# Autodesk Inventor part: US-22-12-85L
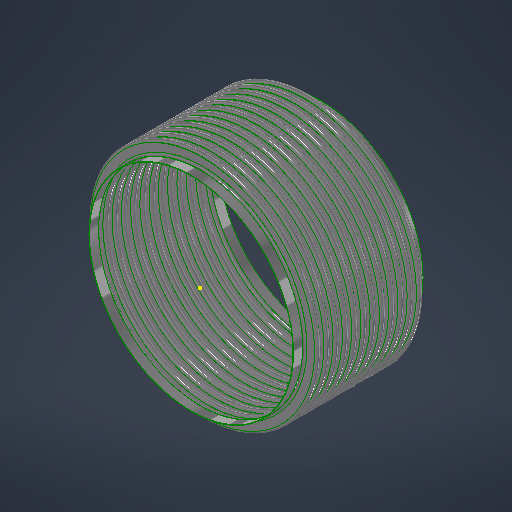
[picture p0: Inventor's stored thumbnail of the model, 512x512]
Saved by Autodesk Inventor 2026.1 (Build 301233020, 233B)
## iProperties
Category: 18 GA (0.048 THICK)
RuleStatus: InUse
Created: 2026-07
Part Number: US-22-12-85L
Project: =STOCK BELLOWS: <Stock Number><SFILL>
Material: ASTM A240-304
Description: =STOCK BELLOWS: <Stock Number>, <SID_> I.D., <SOD_> O.D., <SPLY_> PLY, <Category>, <SNET_CONS> CONS.<PITCH_><STANGENT_> TANGENT<SFILL>
Document SubType Name: Sheet Metal
Designer: LC
Stock Number: U.S-22-12-85L
Surface Area: 659.127 cm^2
Volume: 56.61 cm^3
Sheet Metal Rule: Default
Appearance: STAINLESS STEEL
NET_TUBE: 3.428
COUNTER: 1.500
PBAR: 1.214
PSET: 5.356
PLY: 2
CONS: 2
THK: 0.036
ID: 4.500
OD: 5.500
CONS_: 2
TANGENT: 0.500
PITCH: 0.375
BELLOWS_UPSET: 0.000
NET_CONS: 2
S_CONS: 0
Description_Units: 0
ID_M: 114.30 mm
OD_M: 139.70 mm
THK_M: 0.91 mm
ID_U: 4.500 in
OD_U: 5.500 in
THK_U: 0.036 in
TANGENT2: 0.500
d79: 1.000
d82: 1.000
d83: 26.000
d84: 24.000
d80: 2.571
d81: 10
SID: 2.375
SCONS_: 12
SPITCH: 0.250
SBELLOWS_UPSET: 0.000
SNET_CONS: 12
SS_CONS: 0
SCONS: 8
d174: 8
d177: 0.018
d178: 2.375
d179: 3.000
d180: 0.375
d181: 1.000
d182: 0.000
d190: 8
d191: 1
d192: 1
d193: 8
d194: 0
PART_NUMBER: U.S-22-12-85L
PRESSURE: 85
SIZE: 22.00
STANGENT_: 1.000
d214: 8
d217: 0.030
d218: 6.625
d219: 8.125
d220: 0.500
d221: 1.000
d222: 0.000
d230: 8
d231: 1
d232: 1
d233: 8
d234: 0
STANGENT: 4.000
SPLY_: 1
STHK_: 0.048
SID_: 22.000
SOD_: 24.750
SPITCH_: 1.000
STANGENT__: 1.000
SBELLOWS_UPSET_: 0.000
SDIFF_TAN: 1.000
TAN_TO_TAN: 0.750 in
d252: 2
d275: 2
d287: 0.050
d289: 0.500
d290: 0.000
d263: 2
d265: 1
d268: 2
d269: 0
d286: 2
d288: 1
d291: 2
d292: 0
SOD_NECK: 22 1/8
CFILL: .
SFILL: .
PITCH_: =, <SPITCH_> PITCH,
SREROLL: 0.750
MATTABLE: 20 GA (0.036 THICK)
MESH: ,
CSECT: 2
Author: LC
Keywords: 20 GA (0.036 THICK)
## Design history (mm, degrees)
sketch "Sketch2"
  geometry: L1 (0, -183.595)-(0, 600.956) reference; L2 (58.979, 0)-(57.15, 0); L3 (60.446, -1.467)-(66.554, -1.467); L4 (60.446, -3.296)-(66.554, -3.296); L5 (66.554, -8.058)-(60.446, -8.058); L6 (66.554, -6.229)-(60.446, -6.229); L7 (58.979, -9.525)-(57.15, -9.525); L8 (60.446, 0)-(60.446, -9.525); L9 (66.554, -4.762)-(69.85, -4.763); L10 (57.15, 0)-(57.15, -9.525); L11 (20.376, 102.841)-(20.376, 101.926); L12 (58.262, 488.877)-(58.262, 349.177); L13 (58.262, 479.352)-(58.262, 339.652); L14 (93.133, -58.817)-(93.133, -71.517); L15 (118.746, -66.401)-(118.746, -66.401); L16 (66.554, -6.229)-(66.554, -8.058); L17 (60.446, -6.229)-(60.446, -8.058); L18 (60.446, -7.144)-(66.554, -7.144); L19 (69.85, 0)-(69.85, -9.525); L20 (-66.554, -6.229)-(-66.554, -8.058); L21 (-66.554, -1.467)-(-60.446, -1.467); L22 (-66.554, -3.296)-(-60.446, -3.296); L23 (-60.446, -6.229)-(-66.554, -6.229); L24 (-66.554, -7.144)-(-60.446, -7.144); L25 (-60.446, -8.058)-(-66.554, -8.058); L26 (-60.446, -6.229)-(-60.446, -8.058); L27 (-57.15, -2.522)-(-57.15, -12.047); L28 (-60.446, -4.763)-(-57.15, -4.763); L29 (-66.554, 3.828)-(-66.554, -9.525); L30 (-68.021, 0)-(-69.85, 0); L31 (-69.85, 0)-(-69.85, -9.525); L32 (-68.021, -9.525)-(-69.85, -9.525); A1 r 1.467 centre (60.446, 0) between (58.979, 0) and (60.446, -1.467); A2 r 3.296 centre (60.446, 0) between (57.15, 0) and (60.446, -3.296); A3 r 3.296 centre (66.554, -4.762) between (66.554, -8.058) and (66.554, -1.467); A4 r 1.467 centre (66.554, -4.762) between (66.554, -6.229) and (66.554, -3.296); A5 r 1.467 centre (60.446, -9.525) between (60.446, -8.058) and (58.979, -9.525); A6 r 3.296 centre (60.446, -9.525) between (60.446, -6.229) and (57.15, -9.525); A7 r 2.381 centre (66.554, -4.762) between (66.554, -7.144) and (68.936, -4.762); A8 r 2.381 centre (60.446, -9.525) between (60.446, -7.144) and (58.064, -9.525); A9 r 1.467 centre (-66.554, -9.525) between (-66.554, -8.058) and (-68.021, -9.525); A10 r 1.467 centre (-60.446, -4.763) between (-60.446, -6.229) and (-60.446, -3.296); A11 r 2.381 centre (-60.446, -4.763) between (-60.446, -7.144) and (-58.064, -4.763); A12 r 3.296 centre (-60.446, -4.763) between (-60.446, -8.058) and (-60.446, -1.467); A13 r 2.381 centre (-66.554, -9.525) between (-66.554, -7.144) and (-68.936, -9.525); A14 r 3.296 centre (-66.554, -9.525) between (-66.554, -6.229) and (-69.85, -9.525); A15 r 1.467 centre (-66.554, 0) between (-68.021, 0) and (-66.554, -1.467); A16 r 3.296 centre (-66.554, 0) between (-69.85, 0) and (-66.554, -3.296); 10 further points
  constraints: 62 end point, 38 point on circle, 20 tangent, 16 centre point, 12 parallel, 9 midpoint, 7 vertical, 6 coincident, 6 concentric, 6 point on line, 4 equal radius, 4 perpendicular, 3 horizontal, 1 collinear, 1 horizontal alignment, 10 other
  dimensions: "THK" = 0.9144 distance of L11.start L11.end; "ID" = 114.3 distance of L11.end point (20.376, -12.374); "OD" = 139.7 distance of L12.start L12.end; "PITCH" = 9.525 distance of L12.start L13.start; "TANGENT" = 12.7 distance of L14.start L14.end; "BELLOWS_UPSET" = 0 distance of L15.start L15.end; "d43" = 114.3 diameter of L10 L1 (= ID); "d44" = 139.7 diameter of L9.end L1 (= OD); "d45" = 1.8288 distance between parallel lines of L5 L6 (computed from THK, PLY); "d46" = 3.29565 radius of A3 (computed from PITCH, THK, PLY); "UPSET_PITCH" = 9.525 distance of L2.end L7.end (derived); "SIDEWALL_ANGLE" = 0 deg angle of L3 L9 (derived); "CON_GAP" = 2.9337 distance of point (60.446, -6.229) point (60.446, -3.296) (derived); "TAN1" = 3.74046 dimension on A8 (derived); "TAN2" = 3.74046 dimension on A7 (derived); "LEG1" = 6.1087 distance of L18.start L18.end (derived); "d278" = 1.8288 distance between parallel lines of L25 L23 (derived); "d279" = 3.29565 radius of A12 (derived); "d280" = 9.525 distance of L30.end L31.end (derived); "d281" = 360 deg dimension on L21 L28 (derived); "d282" = 2.9337 distance of point (-66.554, -6.229) point (-66.554, -3.296) (derived); "d283" = 3.74046 dimension on A13 (derived); "d284" = 3.74046 dimension on A11 (derived); "d285" = 6.1087 distance of L24.start L24.end (derived); "d293" = 114.3 diameter of L27 L1 (derived); "d294" = 139.7 diameter of L31 L1 (derived)
  node "Sketch Rectangular Pattern1" dims "d31" = 25.4, "ID" = 114.3
  node "Sketch Rectangular Pattern2" dims "d39" = 25.4, "PITCH" = 9.525
revolve "CONS" stored, may be unused: angle "d48" = 90 deg
node "BELLOW MIDPLANE"
pattern_linear "Rectangular Pattern2" dims "d52" = 9.525 (= UPSET_PITCH)
sketch "Sketch5"
  geometry: C1 r 58.979 at (0, 0) reference; C2 r 57.15 at (0, 0) reference
extrude "TANGENT" new body sketch "Sketch5" distance "d53" = 12.7 (= TANGENT); taper "d54" = 0 deg
revolve "SAMETAN" stored, may be unused: angle "d65" = 90 deg
revolve "DIFFTAN" stored, may be unused: angle "d70" = 90 deg
sketch "Sketch9"
  geometry: L1 (58.391, 0)-(-58.391, 0) reference; L2 (0, -17.78)-(0, 17.78) reference; L3 (41.708, 0)-(-41.708, 0); L4 (41.708, -11.906)-(41.708, 11.906); L5 (29.008, -11.906)-(29.008, 11.906); L6 (15.418, 11.906)-(15.418, -11.906); L7 (-29.008, -11.906)-(-29.008, 11.906); L8 (-41.708, -11.906)-(-41.708, 11.906); L9 (40.914, -11.906)-(40.914, 11.906); L10 (41.708, -11.906)-(40.914, -11.906); L11 (41.708, 11.906)-(40.914, 11.906); L12 (15.815, 11.906)-(15.022, 11.906); L13 (15.022, 11.906)-(15.022, -11.906); L14 (15.022, -11.906)-(15.815, -11.906); L15 (15.815, -11.906)-(15.815, 11.906); L16 (-15.815, 11.906)-(-15.815, -11.906); L17 (-15.418, 11.906)-(-15.418, -11.906); L18 (-15.815, -11.906)-(-15.022, -11.906); L19 (-15.022, -11.906)-(-15.022, 11.906); L20 (-15.022, 11.906)-(-15.815, 11.906); L21 (-41.708, -11.906)-(-40.914, -11.906); L22 (-40.914, -11.906)-(-40.914, 11.906); L23 (-40.914, 11.906)-(-41.708, 11.906); L24 (-41.708, 11.906)-(-41.708, -11.906); L25 (41.708, -0.397)-(-41.708, -0.397); L26 (-41.708, -0.397)-(-41.708, 0.397); L27 (-41.708, 0.397)-(41.708, 0.397); L28 (41.708, 0.397)-(41.708, -0.397); L29 (-41.708, 11.906)-(41.708, 11.906); L30 (41.708, 11.906)-(41.708, 12.7); L31 (41.708, 12.7)-(-41.708, 12.7); L32 (-41.708, 12.7)-(-41.708, 11.906); L33 (41.708, -11.906)-(-41.708, -11.906); L34 (-41.708, -11.906)-(-41.708, -12.7); L35 (-41.708, -12.7)-(41.708, -12.7); L36 (41.708, -12.7)-(41.708, -11.906); 30 further points
  constraints: 68 end point, 13 midpoint, 13 parallel, 8 horizontal, 7 perpendicular, 6 equal length, 3 point on line, 2 vertical, 14 other
  dimensions: "d115" = 23.8125 distance of L4.start L4.end (derived); "d116" = 12.7 distance between parallel lines of L4 L5 (derived); "d117" = 13.58962 distance between parallel lines of L5 L6 (derived); "d125" = 44.42645 distance between parallel lines of L7 L6 (derived); "d127" = 12.7 distance between parallel lines of L8 L7 (derived); "d128" = 26.28962 distance between parallel lines of L6 L4 (derived); "d130" = 83.41607 distance between parallel lines of L8 L4 (derived); "RULER_THK" = 0.79375 distance between parallel lines of L4 L9; "d135" = 0.79375 distance of L13.end L14.end (derived); "d138" = 30.83684 distance of L13.end L16.end (derived); "d143" = 0.79375 distance of L22.end L8.end (derived); "d144" = 0.79375 distance between parallel lines of L27 L25 (derived)
extrude "RULER" join sketch "Sketch9" distance "d149" = 0.79375 (derived); taper "d150" = 0 deg
extrude "BARS" join sketch "Sketch9" distance "d151" = 0.79375 (derived); taper "d152" = 0 deg
pattern_linear "Rectangular Pattern4" dims "d155" = 30.83684 (derived)
sketch "Sketch13"
  geometry: L1 (93.149, -52.467)-(93.149, -77.867); L2 (280.619, 0)-(279.4, 0); L3 (280.619, -25.4)-(279.4, -25.4); L4 (307.365, -19.66)-(286.36, -19.66); L5 (307.365, -18.44)-(286.36, -18.44); L6 (307.365, -12.7)-(314.325, -12.7); L7 (286.36, -5.74)-(307.365, -5.74); L8 (286.36, 0)-(286.36, -25.4); L9 (279.4, 0)-(279.4, -25.4); L10 (58.254, -184.223)-(58.254, -812.873); L11 (58.254, -209.623)-(58.254, -838.273); L12 (58.254, -260.423)-(58.254, -889.073); L13 (58.254, -285.823)-(58.254, -914.473); L14 (58.254, -311.223)-(58.254, -939.873); L15 (58.254, -336.623)-(58.254, -965.273); L16 (58.254, -362.023)-(58.254, -990.673); L17 (58.254, -235.023)-(58.254, -863.673); L18 (20.376, 103.145)-(20.376, 101.926); L19 (286.36, -6.96)-(307.365, -6.96); L20 (0, -1163.716)-(0, 314.289) reference; L21 (-57.15, 0)-(342.9, 0) reference; A1 r 5.74 centre (286.36, 0) between (280.619, 0) and (286.36, -5.74); A2 r 5.74 centre (286.36, -25.4) between (286.36, -19.66) and (280.619, -25.4); A3 r 6.96 centre (286.36, -25.4) between (286.36, -18.44) and (279.4, -25.4); A4 r 5.74 centre (307.365, -12.7) between (307.365, -18.44) and (307.365, -6.96); A5 r 6.96 centre (307.365, -12.7) between (307.365, -19.66) and (307.365, -5.74); A6 r 6.96 centre (286.36, 0) between (279.4, 0) and (286.36, -6.96); 6 further points; 1 other entity
  constraints: 38 end point, 15 point on circle, 9 tangent, 6 centre point, 6 parallel, 5 vertical alignment, 4 point on line, 4 vertical, 3 coincident, 3 concentric, 2 collinear, 2 equal radius, 1 horizontal, 1 perpendicular, 23 other
  dimensions: "SBELLOWS_UPSET_" = 0 distance of point (118.762, -66.401) point (118.762, -66.401); "STOTAL_THK_BELLOW__" = 1.2192 distance between parallel lines of L4 L5 (derived); "d224" = 6.9596 radius of A5 (derived); "d225" = 25.4 distance of L2.end L3.end (derived); "SSIDEWALL_ANGLE_" = 0 deg angle of L7 L6 (derived); "SSCON_GAP_" = 11.4808 distance of point (286.36, -18.44) point (286.36, -6.96) (derived); "d235" = 558.8 diameter of L9 L20 (derived); "d236" = 628.65 diameter of L6.end L20 (derived)
  node "Sketch Rectangular Pattern4" dims "d228" = 25.4
  node "Sketch Rectangular Pattern5" dims "d229" = 25.4
revolve "SBELLOW" stored, may be unused: angle "d197" = 90 deg
pattern_linear "Rectangular Pattern5" dims "d204" = 25.4 (derived)
revolve "STANGENT" stored, may be unused: angle "d240" = 90 deg
revolve "SSAMETAN" stored, may be unused: angle "d241" = 90 deg
revolve "SDIFFTAN" stored, may be unused: angle "d246" = 90 deg
revolve "INVCON" stored, may be unused: angle "d295" = 90 deg
pattern_linear "Rectangular Pattern6" dims "d298" = 9.525 (derived)
revolve "INVTANGENT" stored, may be unused: angle "d302" = 90 deg
revolve "INVSAMETAN" stored, may be unused: angle "d307" = 90 deg
revolve "INVDIFFTAN" stored, may be unused: angle "d312" = 90 deg
sketch "ID BELLOW MOUNT CALC"
  geometry: L1 (44.45, 0)-(38.1, 0); L2 (38.1, 0)-(38.1, 12.7); L3 (38.1, 12.7)-(44.45, 12.7); L4 (44.45, 12.7)-(44.45, 0); L5 (36.513, 12.7)-(34.684, 12.7); L6 (34.684, 12.7)-(34.684, 0); L7 (34.684, 0)-(36.513, 0); L8 (36.513, 0)-(36.513, 12.7); L9 (0, -2.54)-(0, 15.24) reference; L10 (-8.89, 0)-(53.34, 0) reference; 1 further point
  constraints: 16 end point, 5 parallel, 2 collinear, 2 horizontal, 2 perpendicular
  dimensions: "d314" = 12.7 distance of L5.end L6.end (derived); "d315" = 1.8288 distance of L5.start L5.end (derived); "IG" = 1.5875 distance between parallel lines of L2 L8; "PIPE_OD" = 88.9 diameter of L4 L9; "PIPE_WALL" = 6.35 distance of L2.end L3.end; "ID_MT_BELLOW" = 69.3674 diameter of L6 L9 (derived)
revolve "CFILL" stored, may be unused: angle "d320" = 90 deg
pattern_linear "Rectangular Pattern7" dims "d323" = 9.525 (derived)
revolve "SFILL" stored, may be unused: angle "d324" = 90 deg
pattern_linear "Rectangular Pattern8" dims "d327" = 25.4 (derived)
node "STOCK BELLOW MIDPLANE"
sketch "Sketch21"
  geometry: L1 (0, -100.013)-(0, 100.013) reference; L2 (-100.013, 0)-(100.013, 0) reference; L3 (-0.099, 71.437)-(0.099, 71.437); L4 (0.099, 71.437)-(0.099, 55.562); L5 (0.099, 55.562)-(-0.099, 55.562); L6 (-0.099, 55.562)-(-0.099, 71.437); C1 r 55.562 at (0, 0); C2 r 71.437 at (0, 0); 3 further points
  constraints: 8 end point, 2 centre point, 2 coincident, 2 parallel, 2 tangent, 1 horizontal, 1 perpendicular, 1 other
  dimensions: "d329" = 111.125 diameter of C1 (derived); "d330" = 142.875 diameter of C2 (derived); "d331" = 0.19844 distance of L3.start L3.end
extrude "CLAMSHELL" cut sketch "Sketch21" extent not by distance; stored distance "d332" = 0; taper "d333" = 0 deg
pattern_circular "Circular Pattern1" dims angle "d335" = 180 deg (derived)
node "BELLOW"
sketch "Sketch6"
  geometry: L1 (-19.05, 58.979)-(-6.35, 58.979); L2 (-6.35, 58.979)-(-6.35, 57.15); L3 (-6.35, 57.15)-(-19.05, 57.15); L4 (-19.05, 57.15)-(-19.05, 58.979); L5 (2.54, 0)-(-59.69, 0) reference; L6 (-38.1, -108.388)-(-38.1, 156.601) reference; 1 further point
  constraints: 8 end point, 2 parallel, 1 horizontal, 1 perpendicular
  dimensions: "d61" = 12.7 distance of L2.end L3.end (derived); "d62" = 1.8288 distance of L1.end L2.end (derived); "d63" = 114.3 diameter of L3 L5 (derived); "d64" = 19.05 distance between parallel lines of L4 L6 (derived)
sketch "Sketch12"
  geometry: 1 further point
sketch "Sketch14"
  geometry: L1 (-25.4, 280.619)-(0, 280.619); L2 (0, 280.619)-(0, 279.4); L3 (0, 279.4)-(-25.4, 279.4); L4 (-25.4, 279.4)-(-25.4, 280.619); L5 (5.08, 0)-(-30.48, 0) reference; L6 (0, -51.044)-(0, 306.263) reference; 1 further point
  constraints: 8 end point, 2 parallel, 1 collinear, 1 horizontal, 1 perpendicular
  dimensions: "d237" = 1.2192 distance of L3.end L1.start (derived); "d238" = 558.8 diameter of L3 L5 (derived); "d239" = 25.4 distance of L1.start L1.end (derived); "SOD_NECK" = 561.2384 diameter of L1 L5 (derived)
sketch "Sketch15"
  geometry: L1 (-51.044, 0)-(306.263, 0) reference; L2 (279.4, -304.8)-(280.619, -304.8); L3 (280.619, -304.8)-(280.619, -330.2); L4 (280.619, -330.2)-(279.4, -330.2); L5 (279.4, -330.2)-(279.4, -304.8); L6 (0, -398.78)-(0, 81.28) reference; 1 further point
  constraints: 8 end point, 2 parallel, 1 horizontal, 1 perpendicular
  dimensions: "d205" = 25.4 distance of L4.end L2.start (derived); "d206" = 1.2192 distance of L3.end L4.end (derived); "d207" = 558.8 diameter of L5 L6 (derived); "d208" = 304.8 distance between parallel lines of L1 L2 (derived)
node "TANGENT_"
node "SAME_TAN"
sketch "Sketch8"
  geometry: L1 (58.979, -19.05)-(57.15, -19.05); L2 (57.15, -19.05)-(57.15, -31.75); L3 (57.15, -31.75)-(58.979, -31.75); L4 (58.979, -31.75)-(58.979, -19.05); L5 (0, -40.64)-(0, 21.59) reference; L6 (-108.388, 0)-(156.601, 0) reference; 1 further point
  constraints: 8 end point, 2 parallel, 1 horizontal, 1 perpendicular
  dimensions: "d66" = 114.3 diameter of L2 L5 (derived); "TOTAL_THK_BELLOW" = 1.8288 distance of L2.end L3.end (derived); "d68" = 19.05 distance between parallel lines of L1 L6 (derived); "d69" = 12.7 distance of L1.end L2.end (derived)
node "DIFF_TAN"
node "Sketch Rectangular Pattern3" dims "d138" = 30.83684 (derived), "d141" = 25.4
node "SBELLOW_"
node "STANGENT_"
node "SSAME_TAN"
sketch "Sketch16"
  geometry: L1 (280.619, -304.8)-(279.4, -304.8); L2 (279.4, -304.8)-(279.4, -330.2); L3 (279.4, -330.2)-(280.619, -330.2); L4 (280.619, -330.2)-(280.619, -304.8); L5 (0, -398.78)-(0, 81.28) reference; L6 (-51.044, 0)-(306.263, 0) reference; 1 further point
  constraints: 8 end point, 2 parallel, 1 horizontal, 1 perpendicular
  dimensions: "SDIFF_TAN" = 25.4 distance of L3.end L1.start; "d243" = 1.2192 distance of L2.end L3.end (derived); "d244" = 304.8 distance between parallel lines of L1 L6 (derived); "d245" = 558.8 diameter of L2 L5 (derived)
node "SDIFF_TAN"
body "Solid15"
sketch "Sketch17"
  geometry: L1 (69.85, 12.7)-(68.021, 12.7); L2 (68.021, 12.7)-(68.021, 0); L3 (68.021, 0)-(69.85, 0); L4 (69.85, 0)-(69.85, 12.7); L5 (0, -2.54)-(0, 15.24) reference; L6 (-13.97, 0)-(83.82, 0) reference; 2 further points
  constraints: 8 end point, 2 parallel, 1 horizontal, 1 midpoint, 1 perpendicular, 1 point on line
  dimensions: "INVTANGENT" = 12.7 distance of L3.end L1.start (derived); "d300" = 1.8288 distance of L1.start L1.end (derived); "d301" = 139.7 diameter of L4 L5 (derived)
body "Solid16"
sketch "Sketch18"
  geometry: L1 (69.85, -19.05)-(68.021, -19.05); L2 (68.021, -19.05)-(68.021, -31.75); L3 (68.021, -31.75)-(69.85, -31.75); L4 (69.85, -31.75)-(69.85, -19.05); L5 (-13.97, 0)-(83.82, 0) reference; L6 (0, -40.64)-(0, 21.59) reference; 1 further point
  constraints: 8 end point, 2 parallel, 1 horizontal, 1 perpendicular
  dimensions: "d303" = 19.05 distance between parallel lines of L1 L5 (derived); "d304" = 12.7 distance of L3.end L1.start (derived); "d305" = 1.8288 distance of L2.end L3.end (derived); "d306" = 139.7 diameter of L4 L6 (derived)
body "Solid17"
sketch "Sketch19"
  geometry: L1 (69.85, -19.05)-(68.021, -19.05); L2 (68.021, -19.05)-(68.021, -31.75); L3 (68.021, -31.75)-(69.85, -31.75); L4 (69.85, -31.75)-(69.85, -19.05); L5 (0, -40.64)-(0, 21.59) reference; L6 (-13.97, 0)-(83.82, 0) reference; 1 further point
  constraints: 8 end point, 2 parallel, 1 horizontal, 1 perpendicular
  dimensions: "d308" = 12.7 distance of L1.end L2.end (derived); "d309" = 139.7 diameter of L4 L5 (derived); "d310" = 1.8288 distance of L2.end L3.end (derived); "d311" = 19.05 distance between parallel lines of L1 L6 (derived)
body "Solid18"
body "Solid19"
body "Solid20"
other parameters: "BMPL" = -152.4, "PSET" = 136.0424 (computed from OD, THK, PLY) [user parameter], "PBAR" = 30.83684 (= 0.570796 x PITCH + OD - ID) [user parameter; used in 1 equation term], "COUNTER" = 15 [user parameter], "NET_TUBE" = 87.07367 (computed from CONS_, PBAR, TANGENT) [user parameter], "S_CONS" = 0 [user parameter; used in 1 equation term], "ID_M" = 114.3 (= ID) [user parameter], "OD_M" = 139.7 (= OD) [user parameter], "THK_M" = 0.9144 (= THK) [user parameter], "ID_U" = 114.3 (= ID) [user parameter], "OD_U" = 139.7 (= OD) [user parameter], "THK_U" = 0.9144 (= THK) [user parameter], "D_UNITS" = 0 [user parameter], "TANGENT2" = 12.7 [user parameter], "TAN_TO_TAN" = 19.05 [user parameter], "OD_NECK" = 117.9576 [user parameter], "d79" = 25.4, "d80" = 65.29823 [user parameter], "d82" = 25.4, "d83" = 660.4, "d84" = 609.6, "sa_0" = 4, "FRAME_THK" = 0.79375 [user parameter], "CON_FLAT" = 13.58962 [user parameter], "SID" = 60.325 [user parameter], "SPITCH" = 6.35 [user parameter], "STANGENT_" = 25.4 [user parameter], "SBELLOWS_UPSET" = 0 [user parameter], "SS_CONS" = 0 [user parameter], "STAN_TO_TAN_" = 304.8 [user parameter], "d100" = 1.2192 [user parameter], "d191" = 25.4 [user parameter], "d194" = 0 [user parameter], "STANGENT" = 101.6 [user parameter], "d234" = 0 [user parameter], "SUPSET_PITCH_" = 25.4 [user parameter], "d269" = 0 [user parameter], "d287" = 1.27, "d289" = 12.7, "d290" = 0, "d292" = 0 [user parameter], "Thickness" = 3.048 (derived), "KFactor" = 4.4, "BendRadius" = 3.048 (derived), "BendReliefWidth" = 3.048 (derived), "BendReliefDepth" = 1.524 (derived), "CornerReliefSize" = 12.192 (derived), "SeamGap" = 0.00508, "MinimumRemnant" = 6.096 (derived), "TransitionRadius" = 3.048 (derived), "JacobiRadiusSize" = 3.048 (derived), "GapSize" = 3.048 (derived), "SREROLL" = 19.05 [user parameter], "CUR_STK_PITCH" = 25.4 [user parameter], "d328" = -152.4 (derived), "CSECTDEG" = 180 deg [user parameter]
